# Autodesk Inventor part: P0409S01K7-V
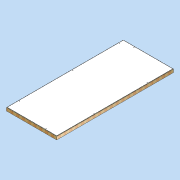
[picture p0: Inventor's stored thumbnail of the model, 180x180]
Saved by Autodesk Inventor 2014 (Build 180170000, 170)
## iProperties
Created: 2011-04
Part Number: P0409S01K7-V
Document SubType Name: Modeling
Designer: david.appleford
Density: 0.179014 g/cm^3
Description: 1w x 2.25w  01 Panel - 7 Locks
Cost Center: £143.00
Mass: 44000 g
Surface Area: 67817.3 cm^2
Volume: 245791 cm^3
Material: Generic
Appearance: Wood (Pine)
Justset: False
Title: 1w x 2.25w  01 Panel - 7 Locks
Author: david.appleford
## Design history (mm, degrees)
sketch "Sketch1"
  geometry: L1 (0, 0)-(1220, 0); L2 (1220, 0)-(1220, 2745); L3 (1220, 2745)-(0, 2745); L4 (0, 2745)-(0, 0); L5 (34, 2711)-(1186, 2711); L6 (1186, 2711)-(1186, 34); L7 (1186, 34)-(34, 34); L8 (34, 34)-(34, 2711)
  constraints: 16 end point, 4 parallel, 2 perpendicular, 1 horizontal, 3 other
  dimensions: "d0" = 1220 distance between parallel lines of L2 L4 (= w); "d1" = 2745 distance between parallel lines of L1 L3 (= 2.25 x w); "d2" = 34 distance between parallel lines of L5 L3 (= 0.5 x t); "d29" = 2677 distance between parallel lines of L7 L5 (derived); "d30" = 1152 distance between parallel lines of L6 L8 (derived)
extrude "Extrusion1" new body sketch "Sketch1" distance "d3" = 68 (= t); taper "d4" = 0 deg
sketch "Sketch2"
  geometry: L1 (1186, 2711)-(1186, 34) reference; L2 (34, 2711)-(1186, 2711) reference; L3 (34, 34)-(34, 2711) reference; L4 (1186, 34)-(34, 34) reference; L5 (1176, 2701)-(1176, 44); L6 (1176, 44)-(44, 44); L7 (44, 44)-(44, 2701); L8 (44, 2701)-(1176, 2701); 1 further point
  constraints: 8 end point, 3 other
  dimensions: "d5" = 10 distance between parallel lines of L8 L2
extrude "Extrusion2" join sketch "Sketch2" distance "d6" = 6 (= sw); taper "d7" = 0 deg
sketch "Sketch3"
  geometry: L1 (-44, 2701)-(-1176, 2701) reference; L2 (-1176, 2701)-(-1176, 44) reference; L3 (-44, 44)-(-44, 2701) reference; L4 (-1176, 44)-(-44, 44) reference; 1 further point
extrude "Extrusion3" join sketch "Sketch3" distance "d8" = 6 (= sw); taper "d9" = 0 deg
sketch "Sketch4"
  geometry: L1 (34, 2711)-(1186, 2711) reference; L2 (1186, 2711)-(1186, 34) reference; L3 (1186, 34)-(34, 34) reference; L4 (34, 34)-(34, 2711) reference; 8 further points
  constraints: 3 vertical alignment
  dimensions: "d10" = 28 distance from line of point (305, 2683) L1 (= k); "d12" = 28 distance from line of L3 point (915, 62) (= k); "d13" = 28 distance from line of point (62, 305) L4 (= k); "d14" = 305 horizontal distance of point (305, 2683) point (0, 0) (= 0.25 x w); "d15" = 610 horizontal distance of point (915, 62) point (305, 2683) (= 0.5 x w); "d16" = 305 vertical distance of point (62, 305) point (0, 0) (= 0.25 x w); "d17" = 1220 distance of point (62, 305) point (62, 1525) (= w); "d19" = 610 vertical distance of point (1158, 915) point (62, 305) (= 0.5 x w); "d20" = 1220 distance of point (1158, 915) point (1158, 2135) (= w); "d31" = 1067.5 distance of point (62, 1525) point (62, 2592.5)
hole "Hole1" sketch "Sketch4" at (305, 2683), (62, 1525), (62, 305), (1158, 2135), (1158, 915), (915, 62), (62, 2592.5) diameter "d22" = 12 (= hd); stored, may be unused: countersink angle "d26" = 90 deg, drill point angle "d28" = 118 deg; dims "d23" = 6, "d24" = 4, "d25" = 2, "d27" = 8
body "Solid1"
node "Projected Loop1"
other parameters: "w" = 1220 [user parameter; used in 8 equation terms], "t" = 68 [user parameter; used in 2 equation terms], "e" = 16 [user parameter], "sw" = 6 [user parameter; used in 2 equation terms], "sc" = 9 [user parameter], "sf" = 12 [user parameter], "k" = 28 [user parameter; used in 3 equation terms], "hd" = 12 [user parameter; used in 1 equation term]
